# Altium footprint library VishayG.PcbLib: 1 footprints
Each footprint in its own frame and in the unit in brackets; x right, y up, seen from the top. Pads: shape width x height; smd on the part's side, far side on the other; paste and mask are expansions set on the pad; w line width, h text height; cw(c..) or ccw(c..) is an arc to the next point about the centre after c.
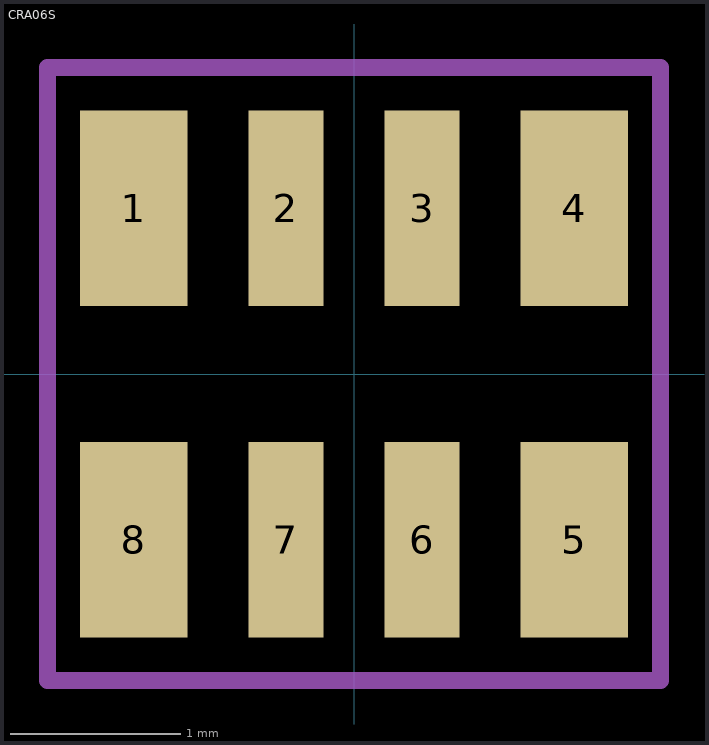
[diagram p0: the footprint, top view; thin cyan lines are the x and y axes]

## CRA06S [mm]
height 0.5
pads (8):
  rect 0.63x1.15 smd mask+0: 1(-1.295,0.975) 4(1.295,0.975) 5(1.295,-0.975) 8(-1.295,-0.975)
  rect 0.44x1.15 smd mask+0: 2(-0.4,0.975) 3(0.4,0.975) 6(0.4,-0.975) 7(-0.4,-0.975)
Mechanical 15:
  lines w0.1: -1.8,-1.8 -1.8,1.8 1.8,1.8 1.8,-1.8 -1.8,-1.8
3D body: height 0.5, standoff 0, extent -1.6,-0.8 1.6,0.8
